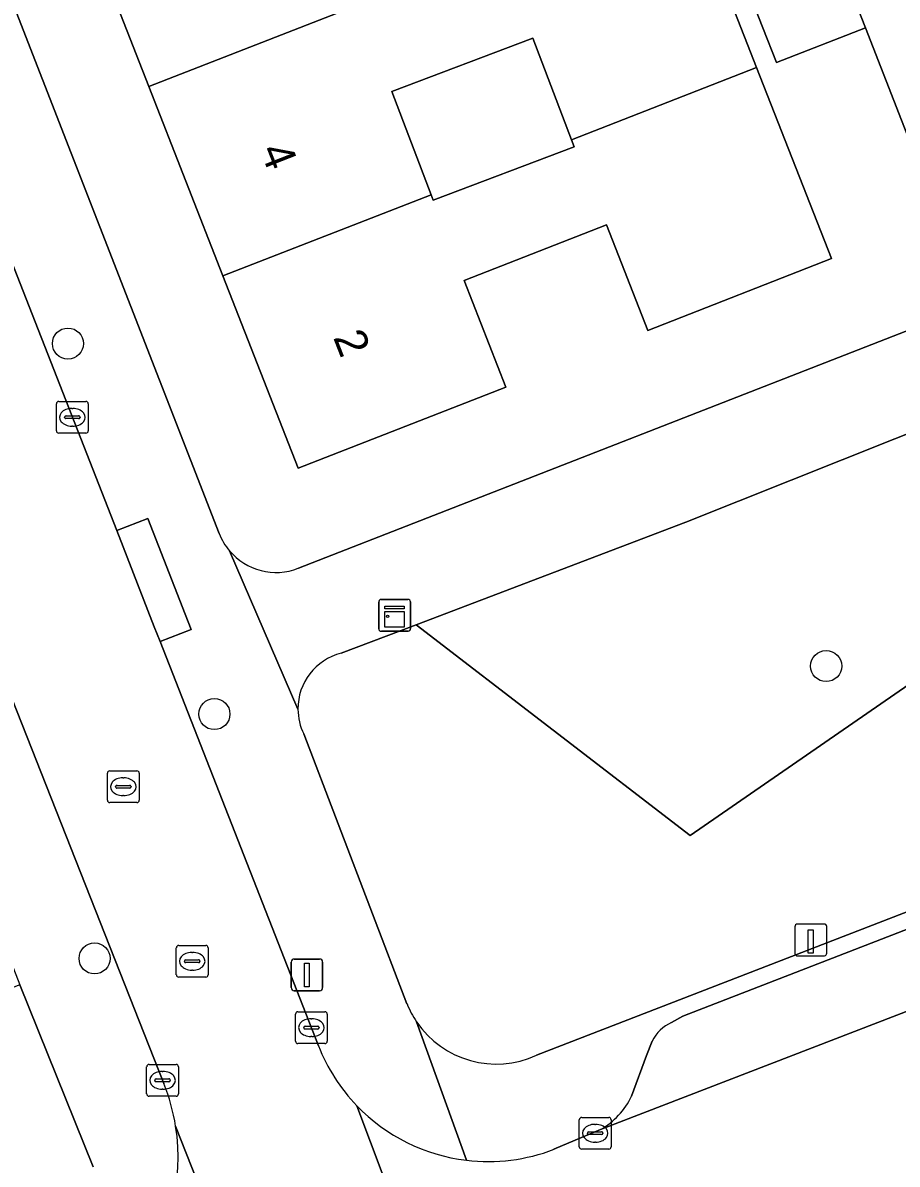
# Model space of a CAD drawing. Extents: x 159680 to 160786, y 387323 to 388340.
# Drawn here: x 160037.27 to 160064.76, y 387669.11 to 387705.01 of the extents above; entities that cross this region are included whole.
import ezdxf

# ---------------------------------------------------------------- set-up
doc = ezdxf.new("R2010")
doc.units = 0
for name, color, linetype in [('IMGEO_Boom', 7, 'Continuous'), ('IMGEO_Erf', 7, 'Continuous'), ('IMGEO_Groenvoorziening', 7, 'Continuous'), ('IMGEO_Kast', 7, 'Continuous'), ('IMGEO_Kolk', 7, 'Continuous'), ('IMGEO_Laadpaal', 7, 'Continuous'), ('IMGEO_Lichtmast', 7, 'Continuous'), ('IMGEO_Pand', 7, 'Continuous'), ('IMGEO_Pand_nummerreeks', 7, 'Continuous'), ('IMGEO_Parkeervlak_open', 7, 'Continuous'), ('IMGEO_Rijbaan_lokaal_open', 7, 'Continuous'), ('IMGEO_Rioolput', 7, 'Continuous'), ('IMGEO_Voetpad_open', 7, 'Continuous')]:
    doc.layers.add(name, color=color, linetype=linetype)

msp = doc.modelspace()

# ---------------------------------------------------------------- linework, layer by layer
at = {"layer": 'IMGEO_Boom'}
for centre in [(160038.684, 387694.919), (160062.527, 387684.775), (160043.288, 387683.265), (160039.522, 387675.579)]:
    msp.add_circle(centre, 0.489, dxfattribs=at)
at = {"layer": 'IMGEO_Erf'}
for points in [[(160063.763, 387704.855), (160060.968, 387703.763), (160060.112, 387705.953), (160062.906, 387707.046), (160049.712, 387741.251), (160047.668, 387746.549), (160047.477, 387746.967)], [(160044.3, 387744.642), (160046.55, 387738.886), (160048.898, 387732.879), (160051.117, 387727.204), (160053.501, 387721.103), (160055.739, 387715.38), (160056.604, 387713.166), (160058.678, 387713.977), (160060.087, 387710.373), (160058.013, 387709.563), (160060.342, 387703.605), (160062.693, 387697.59), (160056.921, 387695.334), (160055.624, 387698.652), (160051.143, 387696.9), (160052.452, 387693.552), (160045.92, 387690.998), (160043.556, 387697.046), (160041.227, 387703.003), (160038.953, 387708.82), (160036.716, 387714.544)], [(160049.712, 387741.251), (160062.906, 387707.046), (160063.763, 387704.855), (160067.164, 387696.141)], [(160024.811, 387736.808), (160043.442, 387688.944)], [(160045.929, 387687.852), (160067.164, 387696.141), (160063.763, 387704.855)]]:
    msp.add_lwpolyline(points, dxfattribs=at)
msp.add_lwpolyline([(160054.519, 387701.332), (160053.305, 387704.53), (160048.873, 387702.847), (160050.105, 387699.603), (160050.172, 387699.426), (160054.604, 387701.109)], close=True, dxfattribs=at)
for centre, radius, start, end in [((160045.184, 387689.609), 1.865, 200.9034, 220.305), ((160045.228, 387689.633), 1.914, 219.9933, 291.4743)]:
    msp.add_arc(centre, radius, start, end, dxfattribs=at)
at = {"layer": 'IMGEO_Groenvoorziening'}
for points in [[(160066.349, 387692.581), (160058.11, 387689.304), (160049.632, 387686.076), (160058.25, 387679.449), (160069.361, 387687.123), (160067.541, 387691.926)], [(160071.824, 387680.505), (160069.361, 387687.123), (160058.25, 387679.449), (160049.632, 387686.076)], [(160049.632, 387686.076), (160047.272, 387685.178)], [(160046.101, 387682.639), (160049.346, 387674.145)], [(160053.42, 387672.531), (160071.219, 387679.422)], [(160039.479, 387669.024), (160037.17, 387674.748), (160009.204, 387663.69), (160010.995, 387658.901), (160034.981, 387668.279)]]:
    msp.add_lwpolyline(points, dxfattribs=at)
for centre, radius, start, end in [((160047.717, 387683.434), 1.8, 104.3049, 180.5422), ((160047.71, 387683.43), 1.793, 180.426, 206.1864), ((160052.128, 387675.269), 3, 202.0022, 214.1215), ((160052.153, 387675.281), 3.028, 214.0468, 294.7328)]:
    msp.add_arc(centre, radius, start, end, dxfattribs=at)
at = {"layer": 'IMGEO_Kast'}
for p, q in [((160048.458, 387685.946), (160048.458, 387686.787)), ((160048.458, 387686.787), (160048.458, 387685.946)), ((160048.533, 387686.871), (160049.374, 387686.871)), ((160049.374, 387686.871), (160048.533, 387686.871)), ((160049.458, 387686.796), (160049.458, 387685.955)), ((160049.458, 387685.955), (160049.458, 387686.796)), ((160049.383, 387685.871), (160048.542, 387685.871)), ((160048.542, 387685.871), (160049.383, 387685.871))]:
    msp.add_line(p, q, dxfattribs=at)
for points in [[(160048.653, 387686.661), (160049.253, 387686.661), (160049.253, 387686.576), (160048.653, 387686.576), (160048.653, 387686.661)], [(160048.653, 387686.486), (160049.253, 387686.486), (160049.253, 387685.997), (160048.653, 387685.997), (160048.653, 387686.486)]]:
    msp.add_lwpolyline(points, dxfattribs=at)
msp.add_circle((160048.737, 387686.335), 0.0377, dxfattribs=at)
for centre, start, end in [((160048.536, 387686.793), 92.4484, 184.2845), ((160048.536, 387686.793), 92.4484, 184.2845), ((160049.38, 387686.793), 2.4484, 94.2845), ((160049.38, 387686.793), 2.4484, 94.2845), ((160048.536, 387685.949), 182.4484, 274.2845), ((160048.536, 387685.949), 182.4484, 274.2845), ((160049.38, 387685.949), 272.4484, 4.2845), ((160049.38, 387685.949), 272.4484, 4.2845)]:
    msp.add_arc(centre, 0.0779, start, end, dxfattribs=at)
at = {"layer": 'IMGEO_Kolk'}
for p, q in [((160038.321, 387692.174), (160038.321, 387693.026)), ((160038.396, 387693.1), (160039.248, 387693.1)), ((160038.809, 387692.88), (160038.834, 387692.88)), ((160039.322, 387693.026), (160039.322, 387692.174)), ((160038.58, 387692.594), (160038.58, 387692.606)), ((160039.018, 387692.557), (160038.62, 387692.557)), ((160038.623, 387692.643), (160039.021, 387692.643)), ((160039.064, 387692.606), (160039.064, 387692.594)), ((160038.832, 387692.32), (160038.807, 387692.32)), ((160039.248, 387692.1), (160038.396, 387692.1)), ((160045.839, 387672.974), (160045.839, 387673.826)), ((160045.914, 387673.9), (160046.766, 387673.9)), ((160046.84, 387673.826), (160046.84, 387672.974)), ((160046.327, 387673.68), (160046.352, 387673.68)), ((160046.098, 387673.394), (160046.098, 387673.406)), ((160046.536, 387673.357), (160046.138, 387673.357)), ((160046.141, 387673.443), (160046.539, 387673.443)), ((160046.35, 387673.12), (160046.325, 387673.12)), ((160046.582, 387673.406), (160046.582, 387673.394)), ((160046.766, 387672.9), (160045.914, 387672.9)), ((160041.159, 387671.317), (160041.159, 387672.169)), ((160041.234, 387672.243), (160042.086, 387672.243)), ((160042.16, 387672.169), (160042.16, 387671.317)), ((160041.418, 387671.737), (160041.418, 387671.749)), ((160041.856, 387671.7), (160041.458, 387671.7)), ((160041.461, 387671.786), (160041.859, 387671.786)), ((160041.647, 387672.023), (160041.672, 387672.023)), ((160041.902, 387671.749), (160041.902, 387671.737)), ((160041.67, 387671.463), (160041.645, 387671.463)), ((160042.086, 387671.243), (160041.234, 387671.243)), ((160054.765, 387669.652), (160054.765, 387670.504)), ((160054.84, 387670.578), (160055.692, 387670.578)), ((160055.253, 387670.358), (160055.278, 387670.358)), ((160055.766, 387670.504), (160055.766, 387669.652)), ((160055.024, 387670.072), (160055.024, 387670.084)), ((160055.462, 387670.035), (160055.064, 387670.035)), ((160055.067, 387670.121), (160055.465, 387670.121)), ((160055.508, 387670.084), (160055.508, 387670.072)), ((160055.692, 387669.578), (160054.84, 387669.578)), ((160055.276, 387669.798), (160055.251, 387669.798))]:
    msp.add_line(p, q, dxfattribs=at)
for points in [[(160038.321, 387692.174), (160038.321, 387693.026)], [(160038.396, 387693.1), (160039.248, 387693.1)], [(160039.322, 387693.026), (160039.322, 387692.174)], [(160039.248, 387692.1), (160038.396, 387692.1)], [(160045.839, 387672.974), (160045.839, 387673.826)], [(160045.914, 387673.9), (160046.766, 387673.9)], [(160046.84, 387673.826), (160046.84, 387672.974)], [(160046.766, 387672.9), (160045.914, 387672.9)], [(160041.159, 387671.317), (160041.159, 387672.169)], [(160041.234, 387672.243), (160042.086, 387672.243)], [(160042.16, 387672.169), (160042.16, 387671.317)], [(160042.086, 387671.243), (160041.234, 387671.243)], [(160054.765, 387669.652), (160054.765, 387670.504)], [(160054.84, 387670.578), (160055.692, 387670.578)], [(160055.766, 387670.504), (160055.766, 387669.652)], [(160055.692, 387669.578), (160054.84, 387669.578)]]:
    msp.add_lwpolyline(points, dxfattribs=at)
for centre, radius, start, end in [((160038.398, 387693.024), 0.0765, 91.552, 178.448), ((160038.398, 387693.024), 0.0765, 91.552, 178.448), ((160039.246, 387693.024), 0.0765, 1.552, 88.448), ((160039.246, 387693.024), 0.0765, 1.552, 88.448), ((160038.62, 387692.603), 0.0403, 85.8775, 175.7526), ((160038.617, 387692.593), 0.0366, 178.938, 274.7102), ((160039.021, 387692.6), 0.043, 264.8664, 352.4533), ((160039.025, 387692.605), 0.0386, 1.7309, 96.639), ((160038.398, 387692.176), 0.0765, 181.552, 268.448), ((160038.398, 387692.176), 0.0765, 181.552, 268.448), ((160039.246, 387692.176), 0.0765, 271.552, 358.448), ((160039.246, 387692.176), 0.0765, 271.552, 358.448), ((160045.916, 387673.824), 0.0765, 91.552, 178.448), ((160045.916, 387673.824), 0.0765, 91.552, 178.448), ((160046.764, 387673.824), 0.0765, 1.552, 88.448), ((160046.764, 387673.824), 0.0765, 1.552, 88.448), ((160046.138, 387673.403), 0.0403, 85.8775, 175.7526), ((160046.135, 387673.393), 0.0366, 178.938, 274.7102), ((160046.539, 387673.4), 0.043, 264.8664, 352.4533), ((160046.543, 387673.405), 0.0386, 1.7309, 96.639), ((160045.916, 387672.976), 0.0765, 181.552, 268.448), ((160045.916, 387672.976), 0.0765, 181.552, 268.448), ((160046.764, 387672.976), 0.0765, 271.552, 358.448), ((160046.764, 387672.976), 0.0765, 271.552, 358.448), ((160041.236, 387672.167), 0.0765, 91.552, 178.448), ((160041.236, 387672.167), 0.0765, 91.552, 178.448), ((160042.084, 387672.167), 0.0765, 1.552, 88.448), ((160042.084, 387672.167), 0.0765, 1.552, 88.448), ((160041.458, 387671.746), 0.0403, 85.8775, 175.7526), ((160041.455, 387671.736), 0.0366, 178.938, 274.7102), ((160041.859, 387671.743), 0.043, 264.8664, 352.4533), ((160041.863, 387671.748), 0.0386, 1.7309, 96.639), ((160041.236, 387671.319), 0.0765, 181.552, 268.448), ((160041.236, 387671.319), 0.0765, 181.552, 268.448), ((160042.084, 387671.319), 0.0765, 271.552, 358.448), ((160042.084, 387671.319), 0.0765, 271.552, 358.448), ((160054.842, 387670.502), 0.0765, 91.552, 178.448), ((160054.842, 387670.502), 0.0765, 91.552, 178.448), ((160055.69, 387670.502), 0.0765, 1.552, 88.448), ((160055.69, 387670.502), 0.0765, 1.552, 88.448), ((160055.064, 387670.081), 0.0403, 85.8775, 175.7526), ((160055.061, 387670.071), 0.0366, 178.938, 274.7102), ((160055.465, 387670.078), 0.043, 264.8664, 352.4533), ((160055.469, 387670.083), 0.0386, 1.7309, 96.639), ((160054.842, 387669.654), 0.0765, 181.552, 268.448), ((160054.842, 387669.654), 0.0765, 181.552, 268.448), ((160055.69, 387669.654), 0.0765, 271.552, 358.448), ((160055.69, 387669.654), 0.0765, 271.552, 358.448)]:
    msp.add_arc(centre, radius, start, end, dxfattribs=at)
for centre, major_axis, ratio, start_param, end_param in [((160038.808, 387692.6), (-0.387, 0.002), 0.722429, 4.712389, 7.853982), ((160038.833, 387692.6), (-0.39, 0.002), 0.717154, 1.570796, 4.712389), ((160046.326, 387673.4), (-0.387, 0.002), 0.722429, 4.712389, 7.853982), ((160046.351, 387673.4), (-0.39, 0.002), 0.717154, 1.570796, 4.712389), ((160041.646, 387671.743), (-0.387, 0.002), 0.722429, 4.712389, 7.853982), ((160041.671, 387671.743), (-0.39, 0.002), 0.717154, 1.570796, 4.712389), ((160055.252, 387670.078), (-0.387, 0.002), 0.722429, 4.712389, 7.853982), ((160055.277, 387670.078), (-0.39, 0.002), 0.717154, 1.570796, 4.712389)]:
    msp.add_ellipse(centre, major_axis=major_axis, ratio=ratio, start_param=start_param, end_param=end_param, dxfattribs=at)
at = {"layer": 'IMGEO_Laadpaal'}
for p, q in [((160061.547, 387676.576), (160061.547, 387675.735)), ((160061.547, 387676.576), (160061.547, 387675.735)), ((160062.463, 387676.66), (160061.622, 387676.66)), ((160062.463, 387676.66), (160061.622, 387676.66)), ((160062.547, 387675.744), (160062.547, 387676.585)), ((160062.547, 387675.744), (160062.547, 387676.585)), ((160061.631, 387675.66), (160062.472, 387675.66)), ((160061.631, 387675.66), (160062.472, 387675.66))]:
    msp.add_line(p, q, dxfattribs=at)
msp.add_lwpolyline([(160061.962, 387676.473), (160062.122, 387676.473), (160062.122, 387675.74), (160061.962, 387675.74), (160061.962, 387676.473)], dxfattribs=at)
for centre, start, end in [((160061.625, 387676.582), 92.4484, 184.2845), ((160061.625, 387676.582), 92.4484, 184.2845), ((160062.469, 387676.582), 2.4484, 94.2845), ((160062.469, 387676.582), 2.4484, 94.2845), ((160061.625, 387675.738), 182.4484, 274.2845), ((160061.625, 387675.738), 182.4484, 274.2845), ((160062.469, 387675.738), 272.4484, 4.2845), ((160062.469, 387675.738), 272.4484, 4.2845)]:
    msp.add_arc(centre, 0.0779, start, end, dxfattribs=at)
at = {"layer": 'IMGEO_Lichtmast'}
for p, q in [((160045.703, 387674.658), (160045.703, 387675.458)), ((160045.703, 387675.458), (160045.703, 387674.658)), ((160045.803, 387675.558), (160046.593, 387675.558)), ((160046.593, 387675.558), (160045.803, 387675.558)), ((160046.693, 387675.458), (160046.693, 387674.658)), ((160046.693, 387674.658), (160046.693, 387675.458)), ((160046.593, 387674.558), (160045.803, 387674.558)), ((160045.803, 387674.558), (160046.593, 387674.558))]:
    msp.add_line(p, q, dxfattribs=at)
msp.add_lwpolyline([(160046.123, 387675.433), (160046.273, 387675.433), (160046.273, 387674.683), (160046.123, 387674.683), (160046.123, 387675.433)], dxfattribs=at)
for centre, start, end in [((160045.803, 387675.458), 90, 180), ((160045.803, 387675.458), 90, 180), ((160046.593, 387675.458), 0, 90), ((160046.593, 387675.458), 360, 90), ((160045.803, 387674.658), 180, 270), ((160045.803, 387674.658), 180, 270), ((160046.593, 387674.658), 270, 0), ((160046.593, 387674.658), 270, 0)]:
    msp.add_arc(centre, 0.1, start, end, dxfattribs=at)
at = {"layer": 'IMGEO_Pand'}
for points in [[(160050.995, 387710.446), (160052.233, 387707.306), (160058.013, 387709.563), (160056.604, 387713.166), (160055.739, 387715.38), (160049.959, 387713.123), (160050.035, 387712.929), (160045.581, 387711.183), (160045.504, 387711.378), (160038.953, 387708.82), (160041.227, 387703.003), (160047.768, 387705.557), (160046.533, 387708.686)], [(160052.233, 387707.306), (160052.316, 387707.096), (160047.855, 387705.336), (160047.768, 387705.557), (160041.227, 387703.003), (160043.556, 387697.046), (160050.105, 387699.603), (160048.873, 387702.847), (160053.305, 387704.53), (160054.519, 387701.332), (160060.342, 387703.605), (160058.013, 387709.563)], [(160060.968, 387703.763), (160063.763, 387704.855), (160062.906, 387707.046), (160060.112, 387705.953)], [(160043.556, 387697.046), (160045.92, 387690.998), (160052.452, 387693.552), (160051.143, 387696.9), (160055.624, 387698.652), (160056.921, 387695.334), (160062.693, 387697.59), (160060.342, 387703.605), (160054.519, 387701.332), (160054.604, 387701.109), (160050.172, 387699.426), (160050.105, 387699.603)]]:
    msp.add_lwpolyline(points, close=True, dxfattribs=at)
at = {"layer": 'IMGEO_Parkeervlak_open'}
for points in [[(160185.066, 387723.299), (160132.762, 387702.9), (160088.425, 387685.547), (160058.019, 387673.764), (160057.664, 387673.563)], [(160055.434, 387670.196), (160089.312, 387683.27), (160133.651, 387700.624)], [(160057.059, 387672.976), (160056.883, 387672.521), (160056.407, 387671.242)]]:
    msp.add_lwpolyline(points, dxfattribs=at)
for centre, radius, start, end in [((160058.196, 387672.41), 1.27, 114.7499, 153.5199), ((160054.276, 387672.249), 2.357, 299.4301, 334.7113)]:
    msp.add_arc(centre, radius, start, end, dxfattribs=at)
at = {"layer": 'IMGEO_Rijbaan_lokaal_open'}
for points in [[(160182.985, 387719.864), (160133.651, 387700.624), (160089.312, 387683.27), (160055.434, 387670.196), (160053.969, 387669.574)], [(160046.561, 387672.828), (160041.583, 387685.544), (160041.4, 387686.011), (160040.216, 387689.036), (160035.472, 387701.152), (160030.768, 387699.317), (160032.302, 387695.434), (160036.769, 387684.127), (160041.702, 387671.64)], [(160047.771, 387670.941), (160053.164, 387656.585)], [(160053.164, 387656.585), (160047.771, 387670.941)], [(160047.986, 387655.306), (160042.071, 387670.3)], [(160042.071, 387670.3), (160047.986, 387655.306)]]:
    msp.add_lwpolyline(points, dxfattribs=at)
for centre, radius, start, end in [((160051.909, 387674.926), 5.744, 201.4177, 223.9207), ((160035.753, 387669.281), 6.399, 9.1618, 21.6304), ((160051.898, 387674.92), 5.733, 223.953, 263.1567), ((160035.787, 387669.292), 6.364, 322.5997, 9.1177), ((160051.898, 387674.927), 5.74, 263.1693, 291.1524)]:
    msp.add_arc(centre, radius, start, end, dxfattribs=at)
at = {"layer": 'IMGEO_Rioolput'}
for p, q in [((160039.925, 387680.553), (160039.925, 387681.405)), ((160040, 387681.479), (160040.852, 387681.479)), ((160040.926, 387681.405), (160040.926, 387680.553)), ((160040.227, 387681.022), (160040.625, 387681.022)), ((160040.413, 387681.259), (160040.438, 387681.259)), ((160040.184, 387680.973), (160040.184, 387680.985)), ((160040.622, 387680.936), (160040.224, 387680.936)), ((160040.436, 387680.699), (160040.411, 387680.699)), ((160040.668, 387680.985), (160040.668, 387680.973)), ((160040.852, 387680.479), (160040, 387680.479)), ((160042.167, 387675.988), (160043.019, 387675.988)), ((160042.092, 387675.062), (160042.092, 387675.914)), ((160042.58, 387675.768), (160042.605, 387675.768)), ((160043.093, 387675.914), (160043.093, 387675.062)), ((160042.351, 387675.482), (160042.351, 387675.494)), ((160042.789, 387675.445), (160042.391, 387675.445)), ((160042.394, 387675.531), (160042.792, 387675.531)), ((160042.835, 387675.494), (160042.835, 387675.482)), ((160043.019, 387674.988), (160042.167, 387674.988)), ((160042.603, 387675.208), (160042.578, 387675.208))]:
    msp.add_line(p, q, dxfattribs=at)
for points in [[(160039.925, 387680.553), (160039.925, 387681.405)], [(160040, 387681.479), (160040.852, 387681.479)], [(160040.926, 387681.405), (160040.926, 387680.553)], [(160040.852, 387680.479), (160040, 387680.479)], [(160042.167, 387675.988), (160043.019, 387675.988)], [(160042.092, 387675.062), (160042.092, 387675.914)], [(160043.093, 387675.914), (160043.093, 387675.062)], [(160043.019, 387674.988), (160042.167, 387674.988)]]:
    msp.add_lwpolyline(points, dxfattribs=at)
for centre, radius, start, end in [((160040.002, 387681.403), 0.0765, 91.552, 178.448), ((160040.002, 387681.403), 0.0765, 91.552, 178.448), ((160040.85, 387681.403), 0.0765, 1.552, 88.448), ((160040.85, 387681.403), 0.0765, 1.552, 88.448), ((160040.224, 387680.982), 0.0403, 85.8775, 175.7526), ((160040.629, 387680.984), 0.0386, 1.7309, 96.639), ((160040.221, 387680.972), 0.0366, 178.938, 274.7102), ((160040.625, 387680.979), 0.043, 264.8664, 352.4533), ((160040.002, 387680.555), 0.0765, 181.552, 268.448), ((160040.002, 387680.555), 0.0765, 181.552, 268.448), ((160040.85, 387680.555), 0.0765, 271.552, 358.448), ((160040.85, 387680.555), 0.0765, 271.552, 358.448), ((160042.169, 387675.912), 0.0765, 91.552, 178.448), ((160042.169, 387675.912), 0.0765, 91.552, 178.448), ((160043.017, 387675.912), 0.0765, 1.552, 88.448), ((160043.017, 387675.912), 0.0765, 1.552, 88.448), ((160042.391, 387675.491), 0.0403, 85.8775, 175.7526), ((160042.388, 387675.481), 0.0366, 178.938, 274.7102), ((160042.792, 387675.488), 0.043, 264.8664, 352.4533), ((160042.796, 387675.493), 0.0386, 1.7309, 96.639), ((160042.169, 387675.064), 0.0765, 181.552, 268.448), ((160042.169, 387675.064), 0.0765, 181.552, 268.448), ((160043.017, 387675.064), 0.0765, 271.552, 358.448), ((160043.017, 387675.064), 0.0765, 271.552, 358.448)]:
    msp.add_arc(centre, radius, start, end, dxfattribs=at)
for centre, major_axis, ratio, start_param, end_param in [((160040.412, 387680.979), (-0.387, 0.002), 0.722429, 4.712389, 7.853982), ((160040.437, 387680.979), (-0.39, 0.002), 0.717154, 1.570796, 4.712389), ((160042.579, 387675.488), (-0.387, 0.002), 0.722429, 4.712389, 7.853982), ((160042.604, 387675.488), (-0.39, 0.002), 0.717154, 1.570796, 4.712389)]:
    msp.add_ellipse(centre, major_axis=major_axis, ratio=ratio, start_param=start_param, end_param=end_param, dxfattribs=at)
at = {"layer": 'IMGEO_Voetpad_open'}
for points in [[(160000.318, 387750), (160020.94, 387697.092), (160021.461, 387695.756), (160027.934, 387698.27), (160029.18, 387695.062), (160031.513, 387689.139), (160033.94, 387682.976), (160034.971, 387680.356), (160036.074, 387677.556), (160037.17, 387674.748), (160039.479, 387669.024)], [(160205.143, 387750), (160183.527, 387741.562), (160182.349, 387741.102), (160129.215, 387720.362), (160127.764, 387719.796), (160068.881, 387696.811), (160067.164, 387696.141), (160045.929, 387687.852)], [(160043.442, 387688.944), (160024.811, 387736.808), (160022.437, 387741.08)], [(160021.961, 387735.751), (160034.24, 387704.299), (160035.472, 387701.152), (160040.216, 387689.036), (160041.193, 387689.419), (160042.373, 387686.406), (160042.561, 387685.927), (160041.583, 387685.544), (160046.561, 387672.828)], [(160057.664, 387673.563), (160058.019, 387673.764), (160088.425, 387685.547), (160132.762, 387702.9)], [(160041.702, 387671.64), (160036.769, 387684.127), (160032.302, 387695.434), (160031.837, 387695.253), (160030.128, 387699.58)], [(160047.272, 387685.178), (160049.632, 387686.076), (160058.11, 387689.304), (160066.349, 387692.581)], [(160045.917, 387683.417), (160043.762, 387688.403)], [(160043.762, 387688.403), (160045.917, 387683.417)], [(160049.346, 387674.145), (160046.101, 387682.639)], [(160071.219, 387679.422), (160053.42, 387672.531)], [(160051.215, 387669.228), (160049.644, 387673.586)], [(160049.644, 387673.586), (160051.215, 387669.228)], [(160056.407, 387671.242), (160056.883, 387672.521), (160057.059, 387672.976)], [(160053.969, 387669.574), (160055.434, 387670.196)]]:
    msp.add_lwpolyline(points, dxfattribs=at)
msp.add_lwpolyline([(160040.216, 387689.036), (160041.4, 387686.011), (160041.583, 387685.544), (160042.561, 387685.927), (160042.373, 387686.406), (160041.193, 387689.419)], close=True, dxfattribs=at)
for centre, radius, start, end in [((160045.184, 387689.609), 1.865, 200.9034, 220.305), ((160045.228, 387689.633), 1.914, 219.9933, 291.4743), ((160047.717, 387683.434), 1.8, 104.3049, 180.5422), ((160047.71, 387683.43), 1.793, 180.426, 206.1864), ((160052.128, 387675.269), 3, 202.0022, 214.1215), ((160052.153, 387675.281), 3.028, 214.0468, 294.7328), ((160058.196, 387672.41), 1.27, 114.7499, 153.5199), ((160051.909, 387674.926), 5.744, 201.4177, 223.9207), ((160035.753, 387669.281), 6.399, 9.1618, 21.6304), ((160054.276, 387672.249), 2.357, 299.4301, 334.7113), ((160051.898, 387674.92), 5.733, 223.953, 263.1567), ((160035.787, 387669.292), 6.364, 322.5997, 9.1177), ((160051.898, 387674.927), 5.74, 263.1693, 291.1524)]:
    msp.add_arc(centre, radius, start, end, dxfattribs=at)

# ---------------------------------------------------------------- texts
at = {"layer": 'IMGEO_Pand_nummerreeks'}
for s, p in [('4', (160044.716, 387701.001)), ('2', (160047.016, 387695.116))]:
    msp.add_text(s, height=1, rotation=291.3512, dxfattribs=at).set_placement(p)

doc.saveas('drawing.dxf')
